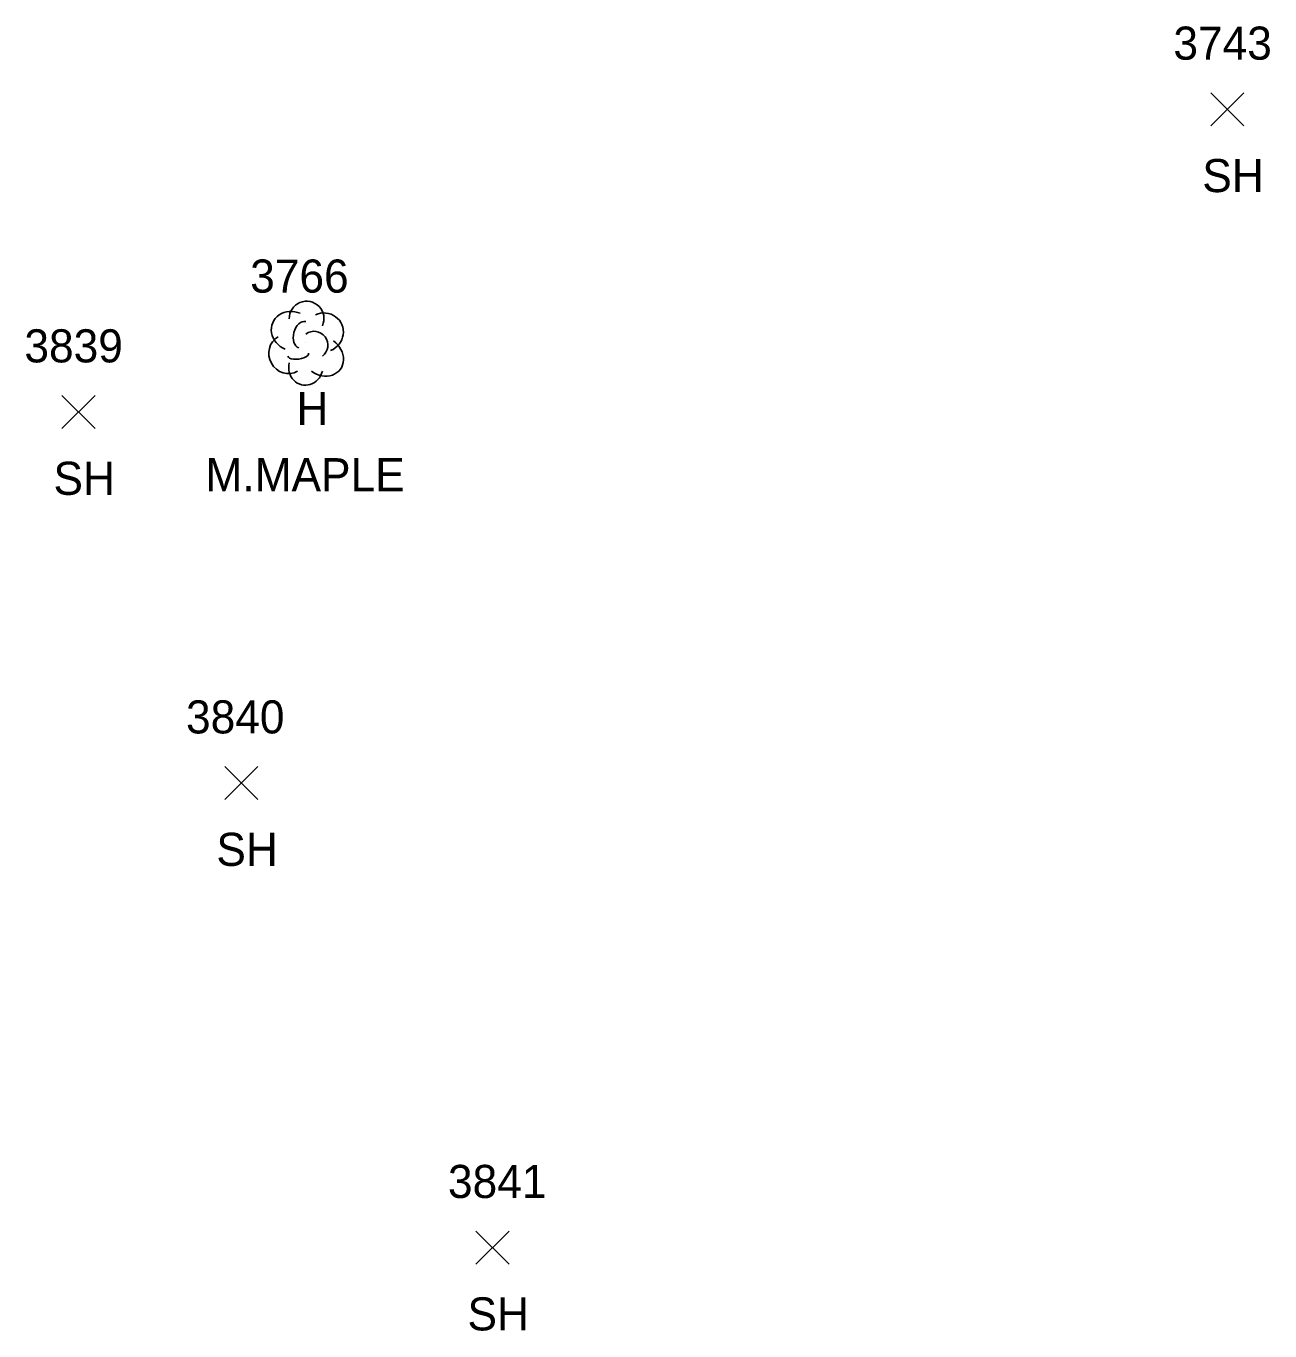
# Model space of a CAD drawing. Extents: x 1520648 to 1523413, y 732854 to 735518.
# Drawn here: x 1521258.4 to 1521333.5, y 733418.5 to 733497.3 of the extents above; entities that cross this region are included whole.
import ezdxf

# ---------------------------------------------------------------- set-up
doc = ezdxf.new("R2010")
doc.units = 0
for name, color, linetype in [('L_A', 7, 'Continuous'), ('L_C', 7, 'Continuous'), ('L_I', 7, 'Continuous'), ('L_TIC', 7, 'Continuous'), ('LTD', 7, 'Continuous')]:
    doc.layers.add(name, color=color, linetype=linetype)

msp = doc.modelspace()

# ---------------------------------------------------------------- linework, layer by layer
at = {"layer": 'L_TIC'}
for points in [[(1521329.964, 733491.265), (1521331.964, 733493.265)], [(1521331.964, 733491.265), (1521329.964, 733493.265)], [(1521260.544, 733472.978), (1521262.544, 733474.978)], [(1521262.544, 733472.978), (1521260.544, 733474.978)], [(1521270.388, 733450.564), (1521272.388, 733452.564)], [(1521272.388, 733450.564), (1521270.388, 733452.564)], [(1521285.563, 733422.5), (1521287.563, 733424.5)], [(1521287.563, 733422.5), (1521285.563, 733424.5)]]:
    msp.add_lwpolyline(points, dxfattribs=at)
at = {"layer": 'LTD'}
msp.add_line((1521275.281, 733478.194), (1521275.281, 733478.194), dxfattribs=at)
msp.add_line((1521275.281, 733478.194), (1521275.281, 733478.194), dxfattribs=at)
msp.add_arc((1521275.328, 733479.628), 1.047, 335.52715, 180.95627, dxfattribs=at)
for centre, major_axis, ratio, start_param, end_param in [((1521274.489, 733478.86), (1.21, -0.512), 0.895232, 1.570796, 4.712389), ((1521275.073, 733478.652), (-0.208, -0.792), 0.645439, 3.141593, 6.283185), ((1521276.323, 733478.777), (-1.141, -0.483), 0.949671, 1.570796, 4.712389), ((1521275.781, 733478.027), (-0.5, 0.667), 0.989748, 3.141593, 6.283185), ((1521274.198, 733477.485), (0.584, -1.042), 0.959034, 3.141593, 6.283185), ((1521276.281, 733477.361), (-1.09, 0.792), 0.841452, 1.570796, 4.712389), ((1521274.823, 733477.444), (-0.625, -0.083), 0.423636, 0, 3.141593), ((1521275.281, 733476.694), (0.265, 1.061), 0.942809, 1.570796, 4.712389)]:
    msp.add_ellipse(centre, major_axis=major_axis, ratio=ratio, start_param=start_param, end_param=end_param, dxfattribs=at)

# ---------------------------------------------------------------- texts
at = {"layer": 'L_A'}
for s, p in [('SH', (1521329.452, 733487.265)), ('H', (1521274.714, 733473.194)), ('SH', (1521260.032, 733468.978)), ('SH', (1521269.877, 733446.564)), ('SH', (1521285.051, 733418.5))]:
    msp.add_text(s, height=2, dxfattribs=at).set_placement(p)
at = {"layer": 'L_C'}
msp.add_text('M.MAPLE', height=2, dxfattribs=at).set_placement((1521269.218, 733469.194))
at = {"layer": 'L_I'}
for s, p in [('3743', (1521327.704, 733495.265)), ('3766', (1521271.919, 733481.194)), ('3839', (1521258.276, 733476.978)), ('3840', (1521268.042, 733454.564)), ('3841', (1521283.87, 733426.5))]:
    msp.add_text(s, height=2, dxfattribs=at).set_placement(p)

doc.saveas('drawing.dxf')
